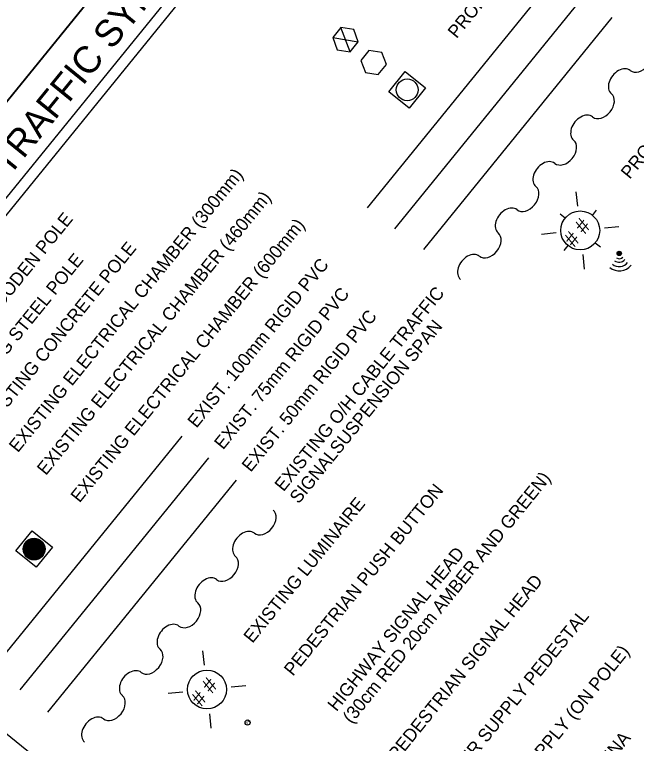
# Model space of a CAD drawing. Extents: x 592613 to 600223, y 4837996 to 4840103.
# Drawn here: x 592912.92 to 592933.72, y 4839262.21 to 4839286.58 of the extents above; entities that cross this region are included whole.
import ezdxf

# ---------------------------------------------------------------- set-up
doc = ezdxf.new("R2010")
doc.units = 0
for name, color, linetype in [('ENG_BORDER', 7, 'Continuous'), ('TCS_100mm-EXIST', 7, 'Continuous'), ('TCS_100mm-NEW', 7, 'Continuous'), ('TCS_50mm-EXIST', 7, 'Continuous'), ('TCS_50mm-NEW', 7, 'Continuous'), ('TCS_75mm-EXIST', 7, 'Continuous'), ('TCS_75mm-NEW', 7, 'Continuous'), ('TCS_ELEC-CHAMBER-EXIST', 7, 'Continuous'), ('TCS_ELEC-CHAMBER-NEW', 7, 'Continuous'), ('TCS_LEGEND', 7, 'Continuous'), ('TCS_LUMINAIRE-EXIST', 7, 'Continuous'), ('TCS_LUMINAIRE-NEW', 7, 'Continuous'), ('TCS_PUSHBUTTON', 7, 'Continuous'), ('TCS_SPAN-EXIST', 7, 'Continuous'), ('TCS_SPAN-NEW', 7, 'Continuous')]:
    doc.layers.add(name, color=color, linetype=linetype)

msp = doc.modelspace()

# ---------------------------------------------------------------- linework, layer by layer
at = {"layer": 'ENG_BORDER'}
for points in [[(593027.682, 4839425.246), (592902.303, 4839270.934)], [(592902.303, 4839270.934), (593006.685, 4839186.123)]]:
    msp.add_lwpolyline(points, dxfattribs=at)
at = {"layer": 'TCS_100mm-EXIST'}
msp.add_line((592912.225, 4839264.73), (592918.531, 4839272.491), dxfattribs=at)
at = {"layer": 'TCS_100mm-NEW'}
msp.add_line((592924.727, 4839280.117), (592931.032, 4839287.878), dxfattribs=at)
at = {"layer": 'TCS_50mm-EXIST'}
msp.add_line((592914.038, 4839263.257), (592920.344, 4839271.018), dxfattribs=at)
at = {"layer": 'TCS_50mm-NEW'}
msp.add_line((592926.606, 4839278.731), (592932.912, 4839286.492), dxfattribs=at)
at = {"layer": 'TCS_75mm-EXIST'}
msp.add_line((592913.116, 4839264.006), (592919.422, 4839271.767), dxfattribs=at)
at = {"layer": 'TCS_75mm-NEW'}
msp.add_line((592925.638, 4839279.424), (592931.944, 4839287.185), dxfattribs=at)
at = {"layer": 'TCS_ELEC-CHAMBER-EXIST'}
for p, q in [((592912.967, 4839268.648), (592913.514, 4839269.321)), ((592913.514, 4839269.321), (592914.188, 4839268.774)), ((592913.282, 4839268.498), (592913.245, 4839268.859)), ((592913.291, 4839268.487), (592913.251, 4839268.872)), ((592913.299, 4839268.476), (592913.257, 4839268.883)), ((592913.307, 4839268.467), (592913.263, 4839268.894)), ((592913.315, 4839268.458), (592913.269, 4839268.904)), ((592913.323, 4839268.45), (592913.275, 4839268.914)), ((592913.332, 4839268.442), (592913.282, 4839268.923)), ((592913.34, 4839268.435), (592913.288, 4839268.932)), ((592913.347, 4839268.429), (592913.295, 4839268.94)), ((592913.355, 4839268.422), (592913.301, 4839268.948)), ((592913.363, 4839268.416), (592913.308, 4839268.955)), ((592913.371, 4839268.411), (592913.314, 4839268.962)), ((592913.379, 4839268.406), (592913.321, 4839268.969)), ((592913.387, 4839268.401), (592913.327, 4839268.975)), ((592913.394, 4839268.396), (592913.334, 4839268.981)), ((592913.402, 4839268.392), (592913.341, 4839268.987)), ((592913.41, 4839268.388), (592913.347, 4839268.993)), ((592913.418, 4839268.384), (592913.354, 4839268.998)), ((592913.425, 4839268.38), (592913.361, 4839269.003)), ((592913.433, 4839268.377), (592913.367, 4839269.008)), ((592913.44, 4839268.373), (592913.374, 4839269.013)), ((592913.448, 4839268.37), (592913.381, 4839269.017)), ((592913.456, 4839268.368), (592913.388, 4839269.022)), ((592913.463, 4839268.365), (592913.395, 4839269.026)), ((592913.471, 4839268.363), (592913.402, 4839269.03)), ((592913.478, 4839268.36), (592913.408, 4839269.033)), ((592913.486, 4839268.358), (592913.415, 4839269.037)), ((592913.493, 4839268.357), (592913.422, 4839269.04)), ((592913.5, 4839268.355), (592913.429, 4839269.043)), ((592913.508, 4839268.353), (592913.436, 4839269.046)), ((592913.515, 4839268.352), (592913.443, 4839269.049)), ((592913.523, 4839268.351), (592913.45, 4839269.052)), ((592913.53, 4839268.35), (592913.457, 4839269.054)), ((592913.537, 4839268.349), (592913.464, 4839269.057)), ((592913.545, 4839268.348), (592913.471, 4839269.059)), ((592913.552, 4839268.348), (592913.478, 4839269.061)), ((592913.559, 4839268.347), (592913.485, 4839269.063)), ((592913.567, 4839268.347), (592913.492, 4839269.065)), ((592913.574, 4839268.347), (592913.5, 4839269.066)), ((592913.581, 4839268.347), (592913.507, 4839269.068)), ((592913.588, 4839268.347), (592913.514, 4839269.069)), ((592913.596, 4839268.347), (592913.521, 4839269.071)), ((592913.603, 4839268.348), (592913.528, 4839269.072)), ((592913.61, 4839268.348), (592913.535, 4839269.072)), ((592913.617, 4839268.349), (592913.542, 4839269.073)), ((592913.625, 4839268.35), (592913.55, 4839269.074)), ((592913.632, 4839268.351), (592913.557, 4839269.074)), ((592913.639, 4839268.352), (592913.564, 4839269.075)), ((592913.646, 4839268.353), (592913.571, 4839269.075)), ((592913.653, 4839268.355), (592913.579, 4839269.075)), ((592913.66, 4839268.356), (592913.586, 4839269.075)), ((592913.667, 4839268.358), (592913.593, 4839269.075)), ((592913.674, 4839268.36), (592913.6, 4839269.074)), ((592913.681, 4839268.362), (592913.608, 4839269.074)), ((592913.688, 4839268.364), (592913.615, 4839269.073)), ((592913.695, 4839268.366), (592913.622, 4839269.072)), ((592913.703, 4839268.369), (592913.63, 4839269.071)), ((592913.71, 4839268.371), (592913.637, 4839269.07)), ((592913.716, 4839268.374), (592913.645, 4839269.069)), ((592913.723, 4839268.377), (592913.652, 4839269.067)), ((592913.73, 4839268.38), (592913.659, 4839269.066)), ((592913.737, 4839268.384), (592913.667, 4839269.064)), ((592913.744, 4839268.387), (592913.674, 4839269.062)), ((592913.751, 4839268.391), (592913.682, 4839269.06)), ((592913.758, 4839268.394), (592913.689, 4839269.057)), ((592913.765, 4839268.398), (592913.697, 4839269.055)), ((592913.772, 4839268.403), (592913.704, 4839269.052)), ((592913.778, 4839268.407), (592913.712, 4839269.049)), ((592913.785, 4839268.412), (592913.72, 4839269.046)), ((592913.792, 4839268.417), (592913.727, 4839269.043)), ((592913.799, 4839268.422), (592913.735, 4839269.039)), ((592913.806, 4839268.427), (592913.743, 4839269.035)), ((592913.812, 4839268.432), (592913.75, 4839269.031)), ((592913.819, 4839268.438), (592913.758, 4839269.027)), ((592913.826, 4839268.444), (592913.766, 4839269.023)), ((592913.832, 4839268.45), (592913.773, 4839269.018)), ((592913.839, 4839268.457), (592913.781, 4839269.013)), ((592913.845, 4839268.464), (592913.789, 4839269.007)), ((592913.852, 4839268.471), (592913.797, 4839269.001)), ((592913.858, 4839268.479), (592913.805, 4839268.995)), ((592913.865, 4839268.487), (592913.813, 4839268.989)), ((592913.871, 4839268.495), (592913.821, 4839268.982)), ((592913.877, 4839268.504), (592913.829, 4839268.974)), ((592913.884, 4839268.514), (592913.837, 4839268.966)), ((592913.89, 4839268.524), (592913.845, 4839268.958)), ((592913.896, 4839268.534), (592913.853, 4839268.949)), ((592913.902, 4839268.546), (592913.862, 4839268.939)), ((592913.908, 4839268.558), (592913.87, 4839268.928)), ((592913.914, 4839268.572), (592913.878, 4839268.916)), ((592913.92, 4839268.586), (592913.887, 4839268.903)), ((592913.925, 4839268.603), (592913.896, 4839268.888)), ((592913.931, 4839268.622), (592913.905, 4839268.87)), ((592913.641, 4839268.101), (592912.967, 4839268.648)), ((592913.227, 4839268.614), (592913.214, 4839268.734)), ((592913.237, 4839268.581), (592913.218, 4839268.768)), ((592913.247, 4839268.558), (592913.223, 4839268.792)), ((592913.256, 4839268.54), (592913.228, 4839268.812)), ((592913.265, 4839268.524), (592913.233, 4839268.83)), ((592913.274, 4839268.51), (592913.239, 4839268.845)), ((592914.188, 4839268.774), (592913.641, 4839268.101)), ((592913.936, 4839268.644), (592913.914, 4839268.849)), ((592913.94, 4839268.674), (592913.925, 4839268.821)), ((592913.941, 4839268.728), (592913.937, 4839268.769))]:
    msp.add_line(p, q, dxfattribs=at)
msp.add_circle((592913.578, 4839268.711), 0.364, dxfattribs=at)
at = {"layer": 'TCS_ELEC-CHAMBER-NEW'}
for p, q in [((592923.837, 4839286.15), (592923.563, 4839285.813)), ((592924.146, 4839285.339), (592923.837, 4839286.15)), ((592924.265, 4839286.081), (592923.837, 4839286.15)), ((592924.42, 4839285.676), (592924.265, 4839286.081)), ((592923.563, 4839285.813), (592924.42, 4839285.676)), ((592923.563, 4839285.813), (592923.718, 4839285.408)), ((592924.146, 4839285.339), (592924.42, 4839285.676)), ((592923.718, 4839285.408), (592924.146, 4839285.339)), ((592924.775, 4839285.388), (592924.501, 4839285.051)), ((592925.203, 4839285.319), (592924.775, 4839285.388)), ((592925.358, 4839284.914), (592925.203, 4839285.319)), ((592924.501, 4839285.051), (592924.656, 4839284.646)), ((592925.084, 4839284.577), (592925.358, 4839284.914)), ((592924.656, 4839284.646), (592925.084, 4839284.577)), ((592925.445, 4839284.005), (592925.992, 4839284.678)), ((592925.992, 4839284.678), (592926.665, 4839284.131)), ((592926.118, 4839283.458), (592925.445, 4839284.005)), ((592926.665, 4839284.131), (592926.118, 4839283.458))]:
    msp.add_line(p, q, dxfattribs=at)
msp.add_circle((592926.055, 4839284.068), 0.367, dxfattribs=at)
at = {"layer": 'TCS_LEGEND'}
for p, q in [((592910.384, 4839277.672), (592924.901, 4839295.539)), ((592910.666, 4839277.443), (592925.183, 4839295.31))]:
    msp.add_line(p, q, dxfattribs=at)
msp.add_lwpolyline([(592905.041, 4839274.303), (592927.104, 4839301.458)], dxfattribs=at)
at = {"layer": 'TCS_LUMINAIRE-EXIST'}
for p, q in [((592919.275, 4839264.824), (592919.225, 4839265.309)), ((592920.167, 4839264.099), (592920.653, 4839264.149)), ((592918.55, 4839263.931), (592918.064, 4839263.881)), ((592919.442, 4839263.206), (592919.492, 4839262.721))]:
    msp.add_line(p, q, dxfattribs=at)
msp.add_circle((592919.359, 4839264.015), 0.651, dxfattribs=at)
at = {"layer": 'TCS_LUMINAIRE-NEW'}
for p, q in [((592931.758, 4839280.175), (592931.708, 4839280.661)), ((592931.337, 4839279.777), (592931.168, 4839279.913)), ((592932.252, 4839279.871), (592932.389, 4839280.04)), ((592932.65, 4839279.45), (592933.136, 4839279.5)), ((592931.033, 4839279.283), (592930.547, 4839279.232)), ((592931.431, 4839278.861), (592931.294, 4839278.693)), ((592932.346, 4839278.956), (592932.515, 4839278.819)), ((592931.925, 4839278.558), (592931.976, 4839278.072))]:
    msp.add_line(p, q, dxfattribs=at)
msp.add_circle((592931.842, 4839279.366), 0.651, dxfattribs=at)
at = {"layer": 'TCS_PUSHBUTTON'}
for p, q in [((592933.084, 4839278.556), (592933.077, 4839278.624)), ((592933.092, 4839278.546), (592933.083, 4839278.636)), ((592933.1, 4839278.539), (592933.089, 4839278.645)), ((592933.108, 4839278.534), (592933.096, 4839278.651)), ((592933.116, 4839278.53), (592933.103, 4839278.657)), ((592933.123, 4839278.527), (592933.11, 4839278.661)), ((592933.131, 4839278.525), (592933.116, 4839278.664)), ((592933.138, 4839278.524), (592933.123, 4839278.667)), ((592933.146, 4839278.524), (592933.131, 4839278.669)), ((592933.153, 4839278.524), (592933.138, 4839278.67)), ((592933.16, 4839278.525), (592933.145, 4839278.67)), ((592933.167, 4839278.527), (592933.152, 4839278.67)), ((592933.174, 4839278.53), (592933.16, 4839278.669)), ((592933.181, 4839278.533), (592933.167, 4839278.667)), ((592933.188, 4839278.537), (592933.175, 4839278.664)), ((592933.194, 4839278.543), (592933.182, 4839278.66)), ((592933.201, 4839278.55), (592933.19, 4839278.655)), ((592933.207, 4839278.558), (592933.198, 4839278.648)), ((592933.213, 4839278.57), (592933.206, 4839278.637)), ((592933.218, 4839278.593), (592933.216, 4839278.616)), ((592933.075, 4839278.577), (592933.072, 4839278.602))]:
    msp.add_line(p, q, dxfattribs=at)
for centre, radius in [((592933.145, 4839278.597), 0.0733), ((592920.717, 4839262.911), 0.0867)]:
    msp.add_circle(centre, radius, dxfattribs=at)
for centre, radius, start, end in [((592933.142, 4839278.556), 0.253, 232.7914, 320.1073), ((592933.149, 4839278.565), 0.145, 230.9061, 320.9061), ((592933.148, 4839278.519), 0.506, 230.9061, 320.9061), ((592933.148, 4839278.519), 0.361, 230.9061, 320.9061)]:
    msp.add_arc(centre, radius, start, end, dxfattribs=at)
at = {"layer": 'TCS_SPAN-EXIST'}
for centre, start_param, end_param in [((592921.259, 4839269.629), 3.141593, 6.283185), ((592920.628, 4839268.854), 0, 3.141593), ((592919.997, 4839268.078), 3.141593, 6.283185), ((592919.366, 4839267.302), 6.283185, 9.424778), ((592918.735, 4839266.526), 3.141593, 6.283185), ((592918.104, 4839265.75), 6.283185, 9.424778), ((592917.473, 4839264.974), 3.141593, 6.283185), ((592916.843, 4839264.198), 0, 3.141593), ((592916.212, 4839263.423), 3.141593, 6.283185), ((592915.581, 4839262.647), 0, 3.141593)]:
    msp.add_ellipse(centre, major_axis=(0.315, 0.388), ratio=0.7, start_param=start_param, end_param=end_param, dxfattribs=at)
at = {"layer": 'TCS_SPAN-NEW'}
for centre, start_param, end_param in [((592933.83, 4839285.101), 3.141593, 6.283185), ((592933.199, 4839284.326), 0, 3.141593), ((592932.568, 4839283.55), 3.141593, 6.283185), ((592931.937, 4839282.774), 6.283185, 9.424778), ((592931.306, 4839281.998), 3.141593, 6.283185), ((592930.675, 4839281.222), 6.283185, 9.424778), ((592930.045, 4839280.446), 3.141593, 6.283185), ((592929.414, 4839279.67), 0, 3.141593), ((592928.783, 4839278.894), 3.141593, 6.283185), ((592928.152, 4839278.119), 0, 3.141593)]:
    msp.add_ellipse(centre, major_axis=(0.315, 0.388), ratio=0.7, start_param=start_param, end_param=end_param, dxfattribs=at)

# ---------------------------------------------------------------- texts
at = {"layer": 'TCS_LEGEND'}
for s, height, p in [('PROPOSED ELECTRICAL CHAMBER (600mm)', 0.43374, (592927.709, 4839285.76)), ('TRAFFIC SYMBOLS LEGEND', 0.90363, (592912.749, 4839281.158)), ('PROPOSED LUMINAIRE', 0.43374, (592933.498, 4839281.057)), ('EXISTING ELECTRICAL CHAMBER (300mm)', 0.43374, (592913.033, 4839271.914)), ('EXISTING ELECTRICAL CHAMBER (460mm)', 0.43374, (592913.971, 4839271.152)), ('EXISTING WOODEN POLE', 0.43374, (592910.327, 4839274.112)), ('EXISTING ELECTRICAL CHAMBER (600mm)', 0.43374, (592915.097, 4839270.237)), ('EXISTING CONCRETE POLE', 0.43374, (592912.085, 4839272.684)), ('EXISTING STEEL POLE', 0.43374, (592911.208, 4839273.396)), ('EXIST. 100mm RIGID PVC', 0.43374, (592919.007, 4839272.734)), ('EXIST. 75mm RIGID PVC', 0.43374, (592919.898, 4839272.01)), ('EXISTING O/H CABLE TRAFFIC', 0.43374, (592921.918, 4839270.609)), ('EXIST. 50mm RIGID PVC', 0.43374, (592920.82, 4839271.26)), ('SIGNALSUSPENSION SPAN', 0.43374, (592922.423, 4839270.199)), ('(30cm RED 20cm AMBER AND GREEN)', 0.43374, (592924.195, 4839262.845)), ('PEDESTRIAN PUSH BUTTON', 0.43374, (592922.233, 4839264.439)), ('EXISTING LUMINAIRE', 0.43374, (592920.879, 4839265.539)), ('HIGHWAY SIGNAL HEAD ', 0.43374, (592923.69, 4839263.255)), ('PEDESTRIAN SIGNAL HEAD', 0.43374, (592925.716, 4839261.609)), ('POWER SUPPLY PEDESTAL', 0.43374, (592927.223, 4839260.384)), ('POWER SUPPLY (ON POLE)', 0.43374, (592928.621, 4839259.248)), ('VEHICLE LOOP DETECTOR', 0.43374, (592931.117, 4839257.22)), ('TSP/ EVP ANTENNA', 0.43374, (592930.057, 4839258.082))]:
    msp.add_text(s, height=height, rotation=50.9061, dxfattribs=at).set_placement(p)
at = {"layer": 'TCS_LUMINAIRE-EXIST'}
msp.add_text('# #', height=0.506, rotation=50.9061, dxfattribs=at).set_placement((592919.163, 4839263.417))
at = {"layer": 'TCS_LUMINAIRE-NEW'}
msp.add_text('# #', height=0.506, rotation=50.9061, dxfattribs=at).set_placement((592931.637, 4839278.773))
at = {"layer": 'TCS_PUSHBUTTON'}
msp.add_text('PB', height=0.0906, rotation=50.9061, dxfattribs=at).set_placement((592920.717, 4839262.845))

doc.saveas('drawing.dxf')
